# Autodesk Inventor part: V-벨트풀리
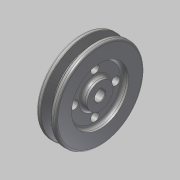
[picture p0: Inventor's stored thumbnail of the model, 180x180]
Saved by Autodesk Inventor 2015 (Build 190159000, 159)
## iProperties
Created: 2015-09
Part Number: V-벨트풀리
Material: 강철, 연강
Document SubType Name: Modeling
Designer: mduedu
Density: 1 g/cm^3
Appearance: 강철
Author: mduedu
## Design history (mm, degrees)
sketch "스케치1"
  geometry: L1 (-9.5, 0)-(9.5, 0); L2 (-9.5, 0)-(-9.5, 42.7); L3 (-9.5, 42.7)-(-4.877, 42.7); L4 (-4.877, 42.7)-(-1.953, 33.7); L5 (-1.953, 33.7)-(1.953, 33.7); L6 (1.953, 33.7)-(4.877, 42.7); L7 (4.877, 42.7)-(9.5, 42.7); L8 (9.5, 42.7)-(9.5, 0); L9 (0, 0)-(0, 33.7); L10 (-9.5, 40)-(9.5, 40); 3 further points
  constraints: 20 end point, 6 point on line, 3 perpendicular, 2 midpoint, 2 parallel, 2 symmetric about line, 1 coincident, 1 collinear, 1 equal length, 1 horizontal, 1 vertical, 1 vertical alignment
  dimensions: "d0" = 19 distance between parallel lines of L8 L2; "d5" = 6.3 distance between parallel lines of L5 L10; "d6" = 8 distance of point (4, 40) point (-4, 40); "d7" = 36 deg angle of L6 L4; "d40" = 2.7 distance between parallel lines of L10 L3; "d82" = 80 diameter of L10 L1; "d83" = 85.4 diameter of L3 L1 (derived)
revolve "회전1" sketch "스케치1" stored, may be unused: angle "d8" = 90 deg
sketch "스케치2"
  geometry: C1 r 12.5 at (0, 0); C2 r 27.5 at (0, 0); 1 further point
  constraints: 2 centre point, 2 coincident
  dimensions: "d9" = 25 diameter of C1; "d41" = 55 diameter of C2
extrude "돌출5" cut sketch "스케치2" distance "d42" = 5; taper "d43" = 0 deg
hole "구멍2" diameter "d46" = 10; stored, may be unused: countersink angle "d50" = 90 deg, drill point angle "d52" = 118 deg; dims "d47" = 6, "d48" = 4, "d49" = 2, "d51" = 8, "d84" = 10, "d85" = 10
sketch "스케치8"
  geometry: L1 (-1.5, 4.77)-(1.5, 4.77); L2 (1.5, 4.77)-(1.5, 6.4); L3 (1.5, 6.4)-(-1.5, 6.4); L4 (-1.5, 6.4)-(-1.5, 4.77); A1 r 5 centre (0, 0) between (-1.5, 4.77) and (1.5, 4.77) reference; 1 further point
  constraints: 8 end point, 2 parallel, 2 point on circle, 1 horizontal, 1 perpendicular
  dimensions: "d53" = 3 distance of L2.end L3.end; "d55" = 11.4 dimension on A1 L3
extrude "돌출6" cut sketch "스케치8" stored distance "d56" = 5; taper "d57" = 0 deg
fillet "모깎기5" dims "d71" = 2, "d72" = 1, "d73" = 0.5
fillet "모깎기7" dims "d75" = 3
fillet "모깎기8" dims "d76" = 3
sketch "스케치10"
  geometry: C1 r 35 at (0, 0); 1 further point
  constraints: 1 centre point, 1 coincident, 1 other
  dimensions: "d77" = 70 diameter of C1
extrude "돌출8" join sketch "스케치10" distance "d80" = 0.5; taper "d81" = 0 deg
chamfer "모따기4" distance "d88" = 0.5; stored, may be unused: second distance "d89" = 2, angle "d90" = 45 deg
sketch "스케치11" dims "d91" = 40
  geometry: C1 r 4 at (0, 20); 2 further points
  constraints: 2 vertical alignment, 1 centre point, 1 coincident, 2 other
  dimensions: "d92" = 8 diameter of C1
extrude "돌출9" cut sketch "스케치11" stored distance "d93" = 10; taper "d94" = 0 deg
node "솔리드1"
mirror "대칭2"
pattern_circular "원형 패턴2" dims angle "d96" = 360 deg
